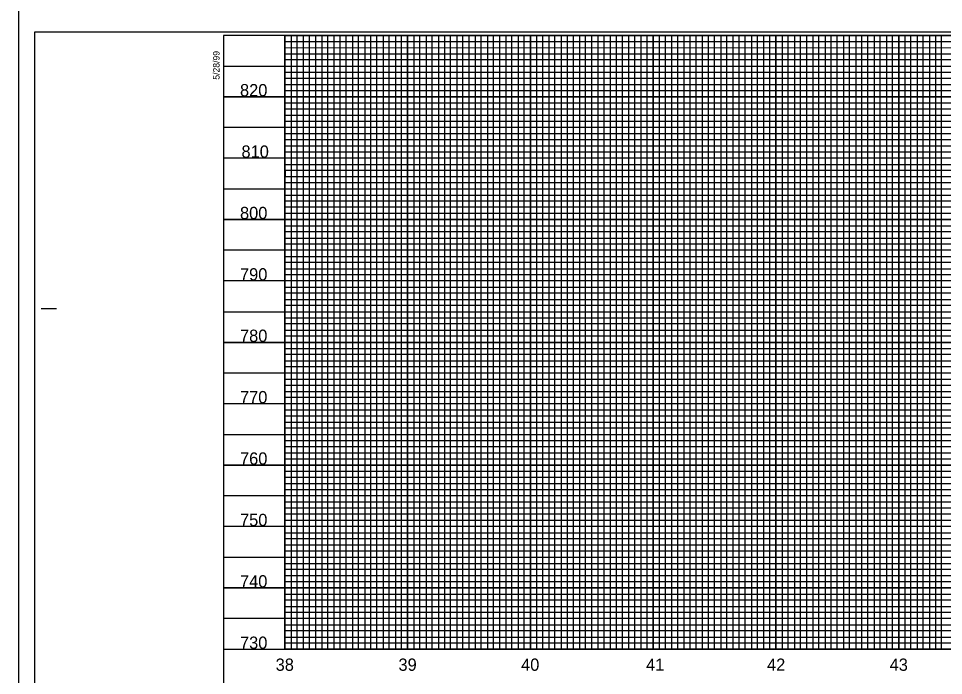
# Model space of a CAD drawing. Extents: x 1755181 to 1757273, y 729911 to 735411.
# Drawn here: x 1755181 to 1755934, y 733764 to 734300 of the extents above; entities that cross this region are included whole.
import ezdxf

# ---------------------------------------------------------------- set-up
doc = ezdxf.new("R2010")
doc.units = 0
for name, color, linetype in [('Exist Vertical Profile Horizontal Axis Label Major', 7, 'Continuous'), ('Exist Vertical Profile Vertical Axis Label', 7, 'Continuous'), ('Scratch_Level_3', 7, 'Continuous'), ('Sheet Cutting Line CELL', 7, 'Continuous'), ('Sheet DOT Grid CELL', 7, 'Continuous'), ('Sheet Plot Border Inside CELL', 7, 'Continuous'), ('Sheet Plot Border Outside CELL', 7, 'Continuous'), ('Sheet Profile CELL', 7, 'Continuous'), ('Sheet Profile Grid Major CELL', 7, 'Continuous'), ('Sheet Profile Grid Middle CELL', 7, 'Continuous'), ('Sheet Profile Grid Minor CELL', 7, 'Continuous')]:
    doc.layers.add(name, color=color, linetype=linetype)

msp = doc.modelspace()

# ---------------------------------------------------------------- linework, layer by layer
at = {"layer": 'Scratch_Level_3'}
msp.add_lwpolyline([(1755397.67, 733785.92), (1755397.67, 734285.78), (1756647.65, 734285.78), (1756647.63, 734052.8), (1756797.72, 734052.78), (1756797.72, 733785.92)], close=True, dxfattribs=at)
at = {"layer": 'Sheet Cutting Line CELL'}
msp.add_line((1755180.67, 734310.78), (1755180.67, 733210.78), dxfattribs=at)
at = {"layer": 'Sheet DOT Grid CELL'}
for p, q in [((1755397.67, 733785.78), (1755397.67, 734285.78)), ((1755447.67, 733785.78), (1755447.67, 734285.78)), ((1755497.67, 733785.78), (1755497.67, 734285.78)), ((1755547.67, 733785.78), (1755547.67, 734285.78)), ((1755597.67, 733785.78), (1755597.67, 734285.78)), ((1755647.67, 733785.78), (1755647.67, 734285.78)), ((1755697.67, 733785.78), (1755697.67, 734285.78)), ((1755747.67, 733785.78), (1755747.67, 734285.78)), ((1755797.67, 733785.78), (1755797.67, 734285.78)), ((1755847.67, 733785.78), (1755847.67, 734285.78)), ((1755897.67, 733785.78), (1755897.67, 734285.78)), ((1756647.62, 734235.78), (1755347.67, 734235.78)), ((1756647.62, 734185.78), (1755347.67, 734185.78)), ((1756647.67, 734135.78), (1755347.67, 734135.78)), ((1756647.63, 734085.78), (1755347.67, 734085.78)), ((1756847.67, 734035.78), (1755347.67, 734035.78)), ((1756847.67, 733985.78), (1755347.67, 733985.78)), ((1756847.67, 733935.78), (1755347.67, 733935.78)), ((1756847.67, 733885.78), (1755347.67, 733885.78)), ((1756847.67, 733835.78), (1755347.67, 733835.78))]:
    msp.add_line(p, q, dxfattribs=at)
at = {"layer": 'Sheet Plot Border Inside CELL'}
msp.add_lwpolyline([(1755193.67, 733233.23), (1756860.17, 733233.23), (1756860.17, 734288.33), (1755193.67, 734288.33)], close=True, dxfattribs=at)
at = {"layer": 'Sheet Plot Border Outside CELL'}
msp.add_lwpolyline([(1755180.67, 733210.78), (1756864.67, 733210.78), (1756864.67, 734310.78), (1755180.67, 734310.78)], close=True, dxfattribs=at)
at = {"layer": 'Sheet Profile CELL'}
for p, q in [((1755199.17, 734063.28), (1755211.67, 734063.28)), ((1755347.67, 733785.78), (1756847.67, 733785.78))]:
    msp.add_line(p, q, dxfattribs=at)
msp.add_lwpolyline([(1756847.67, 734285.78), (1755347.67, 734285.78), (1755347.67, 733235.78), (1756847.67, 733235.78)], close=True, dxfattribs=at)
at = {"layer": 'Sheet Profile Grid Major CELL'}
for points in [[(1755397.67, 734285.78), (1755397.67, 733785.78), (1755447.67, 733785.78), (1755447.67, 734285.78), (1755497.67, 734285.78), (1755497.67, 733785.78), (1755547.67, 733785.78), (1755547.67, 734285.78), (1755597.67, 734285.78), (1755597.67, 733785.78), (1755647.67, 733785.78), (1755647.67, 734285.78), (1755697.67, 734285.78), (1755697.67, 733785.78), (1755747.67, 733785.78), (1755747.67, 734285.78), (1755797.67, 734285.78), (1755797.67, 733785.78), (1755847.67, 733785.78), (1755847.67, 734285.78), (1755897.67, 734285.78), (1755897.67, 733785.78), (1755947.67, 733785.78)], [(1755347.67, 734235.78), (1756647.67, 734235.78)], [(1756647.67, 734185.78), (1755347.67, 734185.78), (1755347.67, 734135.78), (1756647.67, 734135.78)], [(1756647.63, 734085.78), (1755347.67, 734085.78), (1755347.67, 734035.78), (1756847.67, 734035.78)], [(1756847.67, 733985.78), (1755347.67, 733985.78), (1755347.67, 733935.78), (1756847.67, 733935.78)], [(1756847.67, 733885.78), (1755347.67, 733885.78), (1755347.67, 733885.78), (1755347.67, 733835.78), (1756847.67, 733835.78)]]:
    msp.add_lwpolyline(points, dxfattribs=at)
at = {"layer": 'Sheet Profile Grid Middle CELL'}
msp.add_line((1755347.67, 734260.78), (1756647.62, 734260.78), dxfattribs=at)
for points in [[(1755422.67, 734285.78), (1755422.67, 733785.78), (1755472.67, 733785.78), (1755472.67, 734285.78), (1755522.67, 734285.78), (1755522.67, 733785.78), (1755572.67, 733785.78), (1755572.67, 734285.78), (1755622.67, 734285.78), (1755622.67, 733785.78), (1755672.67, 733785.78), (1755672.67, 734285.78), (1755722.67, 734285.78), (1755722.67, 733785.78), (1755772.67, 733785.78), (1755772.67, 734285.78), (1755822.67, 734285.78), (1755822.67, 733785.78), (1755872.67, 733785.78), (1755872.67, 734285.78), (1755922.67, 734285.78), (1755922.67, 733785.78), (1755972.67, 733785.78)], [(1756647.67, 734210.78), (1755347.67, 734210.78), (1755347.67, 734160.78), (1756647.67, 734160.78)], [(1756647.62, 734110.78), (1755347.67, 734110.78), (1755347.67, 734060.78), (1756647.63, 734060.78)], [(1756847.67, 734010.78), (1755347.67, 734010.78), (1755347.67, 733960.78), (1756847.67, 733960.78)], [(1756847.67, 733910.78), (1755347.67, 733910.78), (1755347.67, 733860.78), (1756847.67, 733860.78)], [(1756847.67, 733810.78), (1755347.67, 733810.78)]]:
    msp.add_lwpolyline(points, dxfattribs=at)
at = {"layer": 'Sheet Profile Grid Minor CELL'}
for p, q in [((1755397.67, 734280.78), (1756647.67, 734280.78)), ((1755397.67, 734275.78), (1755397.67, 734275.78)), ((1756647.67, 734275.78), (1755397.67, 734275.43)), ((1755397.67, 734270.78), (1756647.67, 734270.78)), ((1756647.62, 734150.78), (1755397.67, 734150.78)), ((1756647.67, 734145.78), (1755397.67, 734145.78)), ((1756647.67, 734140.78), (1755397.67, 734140.78)), ((1755397.67, 734130.78), (1756647.67, 734130.78)), ((1756647.67, 734125.78), (1755397.67, 734125.78)), ((1755397.67, 734120.78), (1756647.62, 734120.78)), ((1756647.62, 734100.78), (1755397.67, 734100.78)), ((1755397.67, 734095.78), (1756647.62, 734095.78)), ((1756647.63, 734075.78), (1755397.67, 734075.78)), ((1755397.67, 734070.78), (1756647.63, 734070.78)), ((1756797.67, 734050.78), (1755397.67, 734050.78)), ((1755397.67, 734045.78), (1756797.67, 734045.78)), ((1756797.67, 734040.78), (1755397.67, 734040.78)), ((1755397.67, 734030.78), (1756797.67, 734030.78)), ((1756797.67, 734025.78), (1755397.67, 734025.78)), ((1755397.67, 734020.78), (1756797.67, 734020.78)), ((1756797.67, 734015.78), (1755397.67, 734015.78)), ((1755397.67, 734005.78), (1756797.67, 734005.78)), ((1756797.67, 734000.78), (1755397.67, 734000.78)), ((1755397.67, 733995.78), (1756797.67, 733995.78)), ((1756797.67, 733990.78), (1755397.67, 733990.78)), ((1755397.67, 733980.78), (1756797.67, 733980.78)), ((1756797.67, 733975.78), (1755397.67, 733975.78)), ((1755397.67, 733970.78), (1756797.67, 733970.78)), ((1756797.67, 733965.78), (1755397.67, 733965.78)), ((1755397.67, 733955.78), (1756797.67, 733955.78)), ((1756797.67, 733950.78), (1755397.67, 733950.78)), ((1755397.67, 733945.78), (1756797.67, 733945.78)), ((1756797.67, 733940.78), (1755397.67, 733940.78)), ((1755397.67, 733930.78), (1756797.67, 733930.78)), ((1756797.67, 733925.78), (1755397.67, 733925.78)), ((1755397.67, 733920.78), (1756797.67, 733920.78)), ((1756797.67, 733915.78), (1755397.67, 733915.78)), ((1755397.67, 733905.78), (1756797.67, 733905.78)), ((1756797.67, 733900.78), (1755397.67, 733900.78)), ((1756797.67, 733895.78), (1755397.67, 733895.78)), ((1756797.67, 733890.78), (1755397.67, 733890.78)), ((1755397.67, 733880.78), (1756797.67, 733880.78)), ((1756797.67, 733875.78), (1755397.67, 733875.78)), ((1755397.67, 733870.78), (1756797.67, 733870.78)), ((1756797.67, 733865.78), (1755397.67, 733865.78)), ((1755397.67, 733855.78), (1756797.67, 733855.78)), ((1756797.67, 733850.78), (1755397.67, 733850.78)), ((1755397.67, 733845.78), (1756797.67, 733845.78)), ((1756797.67, 733840.78), (1755397.67, 733840.78)), ((1755397.67, 733830.78), (1756797.67, 733830.78)), ((1756797.67, 733825.78), (1755397.67, 733825.78)), ((1755397.67, 733820.78), (1756797.67, 733820.78)), ((1756797.67, 733815.78), (1755397.67, 733815.78)), ((1755397.67, 733805.78), (1756797.67, 733805.78)), ((1756797.67, 733800.78), (1755397.67, 733800.78)), ((1755397.67, 733795.78), (1756797.67, 733795.78))]:
    msp.add_line(p, q, dxfattribs=at)
for points in [[(1755402.67, 734285.78), (1755402.67, 733785.78), (1755407.67, 733785.78), (1755407.67, 734285.78), (1755412.67, 734285.78), (1755412.67, 733785.78), (1755417.67, 733785.78), (1755417.67, 734285.78), (1755427.67, 734285.78), (1755427.67, 733785.78), (1755432.67, 733785.78), (1755432.67, 734285.78), (1755437.67, 734285.78), (1755437.67, 733785.78), (1755442.67, 733785.78), (1755452.67, 733785.78), (1755457.67, 733785.78), (1755457.67, 734285.78), (1755462.67, 734285.78), (1755462.67, 733785.78), (1755467.67, 733785.78), (1755467.67, 734285.78), (1755477.67, 734285.78), (1755477.67, 733785.78), (1755482.67, 733785.78), (1755482.67, 734285.78), (1755487.67, 734285.78), (1755487.67, 733785.78), (1755492.67, 733785.78), (1755492.67, 734285.78), (1755502.67, 734285.78), (1755502.67, 733785.78), (1755507.67, 733785.78), (1755507.67, 734285.78), (1755512.67, 734285.78), (1755512.67, 733785.78), (1755517.67, 733785.78), (1755517.67, 734285.78), (1755527.67, 734285.78), (1755527.67, 733785.78), (1755532.67, 733785.78), (1755532.67, 734285.78), (1755537.67, 734285.78), (1755537.67, 733785.78), (1755542.67, 733785.78), (1755542.67, 734285.78), (1755552.67, 734285.78), (1755552.67, 733785.78), (1755557.67, 733785.78), (1755557.67, 734285.78), (1755562.67, 734285.78), (1755562.67, 733785.78), (1755567.67, 733785.78), (1755567.67, 734285.78), (1755577.67, 734285.78), (1755577.67, 733785.78), (1755582.67, 733785.78), (1755582.67, 734285.78), (1755587.67, 734285.78), (1755587.67, 733785.78), (1755592.67, 733785.78), (1755592.67, 734285.78), (1755602.67, 734285.78), (1755602.67, 733785.78), (1755607.67, 733785.78), (1755607.67, 734285.78), (1755612.67, 734285.78), (1755612.67, 733785.78)], [(1755442.67, 733785.78), (1755442.67, 734285.78), (1755452.67, 734285.78), (1755452.67, 733785.78)], [(1755612.67, 733785.78), (1755617.67, 733785.78), (1755617.67, 734285.78), (1755627.67, 734285.78), (1755627.67, 733785.78), (1755632.67, 733785.78), (1755632.67, 734285.78), (1755637.67, 734285.78), (1755637.67, 733785.78), (1755642.67, 733785.78), (1755642.67, 734285.78), (1755652.67, 734285.78), (1755652.67, 733785.78), (1755657.67, 733785.78), (1755657.67, 734285.78), (1755662.67, 734285.78), (1755662.67, 733785.78), (1755667.67, 733785.78), (1755667.67, 734285.78), (1755677.67, 734285.78), (1755677.67, 733785.78), (1755682.67, 733785.78), (1755682.67, 734285.78), (1755687.67, 734285.78), (1755687.67, 733785.78), (1755692.67, 733785.78), (1755692.67, 734285.78), (1755702.67, 734285.78), (1755702.67, 733785.78), (1755707.67, 733785.78), (1755707.67, 734285.78), (1755712.67, 734285.78), (1755712.67, 733785.78), (1755717.67, 733785.78), (1755717.67, 734285.78), (1755727.67, 734285.78), (1755727.67, 733785.78), (1755732.67, 733785.78), (1755732.67, 734285.78), (1755737.67, 734285.78), (1755737.67, 733785.78), (1755742.67, 733785.78), (1755742.67, 734285.78), (1755752.67, 734285.78), (1755752.67, 733785.78), (1755757.67, 733785.78), (1755757.67, 734285.78), (1755762.67, 734285.78), (1755762.67, 733785.78), (1755767.67, 733785.78), (1755767.67, 734285.78), (1755777.67, 734285.78), (1755777.67, 733785.78), (1755782.67, 733785.78), (1755782.67, 734285.78), (1755787.67, 734285.78), (1755787.67, 733785.78), (1755792.67, 733785.78), (1755792.67, 734285.78), (1755802.67, 734285.78), (1755802.67, 733785.78), (1755807.67, 733785.78), (1755807.67, 734285.78), (1755812.67, 734285.78), (1755812.67, 733785.78), (1755817.67, 733785.78), (1755817.67, 734285.78), (1755827.67, 734285.78), (1755827.67, 733785.78), (1755832.67, 733785.78), (1755832.67, 734285.78), (1755837.67, 734285.78), (1755837.67, 733785.78), (1755842.67, 733785.78), (1755842.67, 734285.78), (1755852.67, 734285.78), (1755852.67, 733785.78), (1755857.67, 733785.78), (1755857.67, 734285.78), (1755862.67, 734285.78), (1755862.67, 733785.78), (1755867.67, 733785.78), (1755867.67, 734285.78), (1755877.67, 734285.78), (1755877.67, 733785.78), (1755882.67, 733785.78), (1755882.67, 734285.78), (1755887.67, 734285.78), (1755887.67, 733785.78), (1755892.67, 733785.78), (1755892.67, 734285.78), (1755902.67, 734285.78), (1755902.67, 733785.78), (1755907.67, 733785.78), (1755907.67, 734285.78), (1755912.67, 734285.78), (1755912.67, 733785.78), (1755917.67, 733785.78), (1755917.67, 734285.78), (1755927.67, 734285.78)], [(1755927.67, 734285.78), (1755927.67, 733785.78), (1755932.67, 733785.78), (1755932.67, 734285.78), (1755937.67, 734285.78)], [(1756647.67, 734265.78), (1755397.67, 734265.78), (1755397.67, 734255.78), (1756647.67, 734255.78)], [(1756647.62, 734250.78), (1755397.67, 734250.78), (1755397.67, 734245.78), (1756647.67, 734245.78)], [(1756647.67, 734240.78), (1755397.67, 734240.78), (1755397.67, 734230.78), (1756647.67, 734230.78)], [(1756647.67, 734225.78), (1755397.67, 734225.78), (1755397.67, 734220.78), (1756647.67, 734220.78)], [(1756647.67, 734215.78), (1755397.67, 734215.78), (1755397.67, 734205.78), (1756647.67, 734205.78)], [(1756647.67, 734200.78), (1755397.67, 734200.78), (1755397.67, 734195.78), (1756647.67, 734195.78)], [(1756647.67, 734190.78), (1755397.67, 734190.78), (1755397.67, 734180.78), (1756647.67, 734180.78)], [(1756647.67, 734175.68), (1755397.77, 734175.68), (1755397.77, 734170.78), (1756647.67, 734170.78)], [(1756647.67, 734165.78), (1755397.67, 734165.78), (1755397.67, 734155.78), (1756647.67, 734155.78)], [(1756647.62, 734115.78), (1755397.67, 734115.78), (1755397.67, 734105.78), (1756647.62, 734105.78)], [(1756647.62, 734090.78), (1755397.67, 734090.78), (1755397.67, 734080.78), (1756647.63, 734080.78)], [(1756647.63, 734065.78), (1755397.67, 734065.78), (1755397.67, 734055.78), (1756647.63, 734055.78)], [(1756797.67, 733790.78), (1755397.67, 733790.78)]]:
    msp.add_lwpolyline(points, dxfattribs=at)

# ---------------------------------------------------------------- texts
at = {"layer": 'Exist Vertical Profile Horizontal Axis Label Major'}
for s, p in [('38', (1755390.14, 733768.28)), ('39', (1755490.18, 733768.28)), ('40', (1755590.06, 733768.28)), ('41', (1755691.89, 733768.28)), ('42', (1755790.44, 733768.28)), ('43', (1755890.28, 733768.28))]:
    msp.add_text(s, height=10, dxfattribs=at).set_placement(p)
at = {"layer": 'Exist Vertical Profile Vertical Axis Label'}
for s, p in [('820', (1755361.1, 734236.17)), ('810', (1755362.3, 734186.17)), ('800', (1755361.1, 734136.17)), ('790', (1755361.1, 734086.17)), ('780', (1755361.1, 734036.17)), ('770', (1755361.1, 733986.17)), ('760', (1755361.1, 733936.17)), ('750', (1755361.1, 733886.17)), ('740', (1755361.1, 733836.17)), ('730', (1755361.1, 733786.17))]:
    msp.add_text(s, height=10, dxfattribs=at).set_placement(p)
at = {"layer": 'Sheet Profile CELL'}
msp.add_text('5/28/99', height=5.25, rotation=90, dxfattribs=at).set_placement((1755344.43, 734249.7))

doc.saveas('drawing.dxf')
